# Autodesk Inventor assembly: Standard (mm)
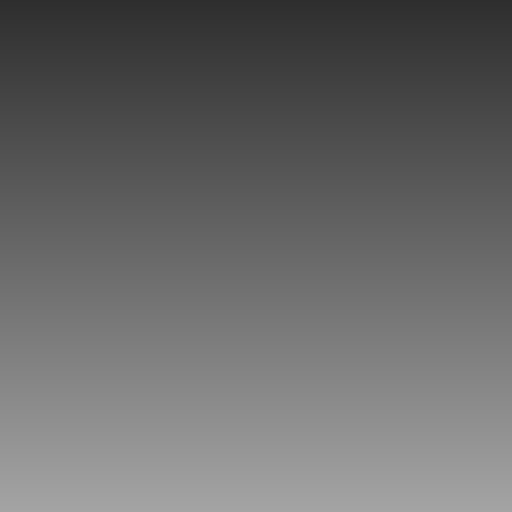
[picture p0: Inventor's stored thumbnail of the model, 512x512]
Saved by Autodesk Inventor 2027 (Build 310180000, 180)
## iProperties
Created: 2002-07
Part Number: Standard (mm)
Document SubType Name: Assembly
Control State: 0
Master: False
Checked Out: False
Shininess: 64.0
Length Units: 11269
Angle Units: 11279
Time Units: 11290
Mass Units: 11283
Length Display Precision: 3
Angle Display Precision: 2
Compacted: True
Density: 0.0
Volumn: 0.0
Area: 0.0
PropertySet Name: Model Information
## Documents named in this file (1)
- D:\AUTOBUILD\inventor\Application\App\Templates\en-US\Metric\Standard (mm).iam
